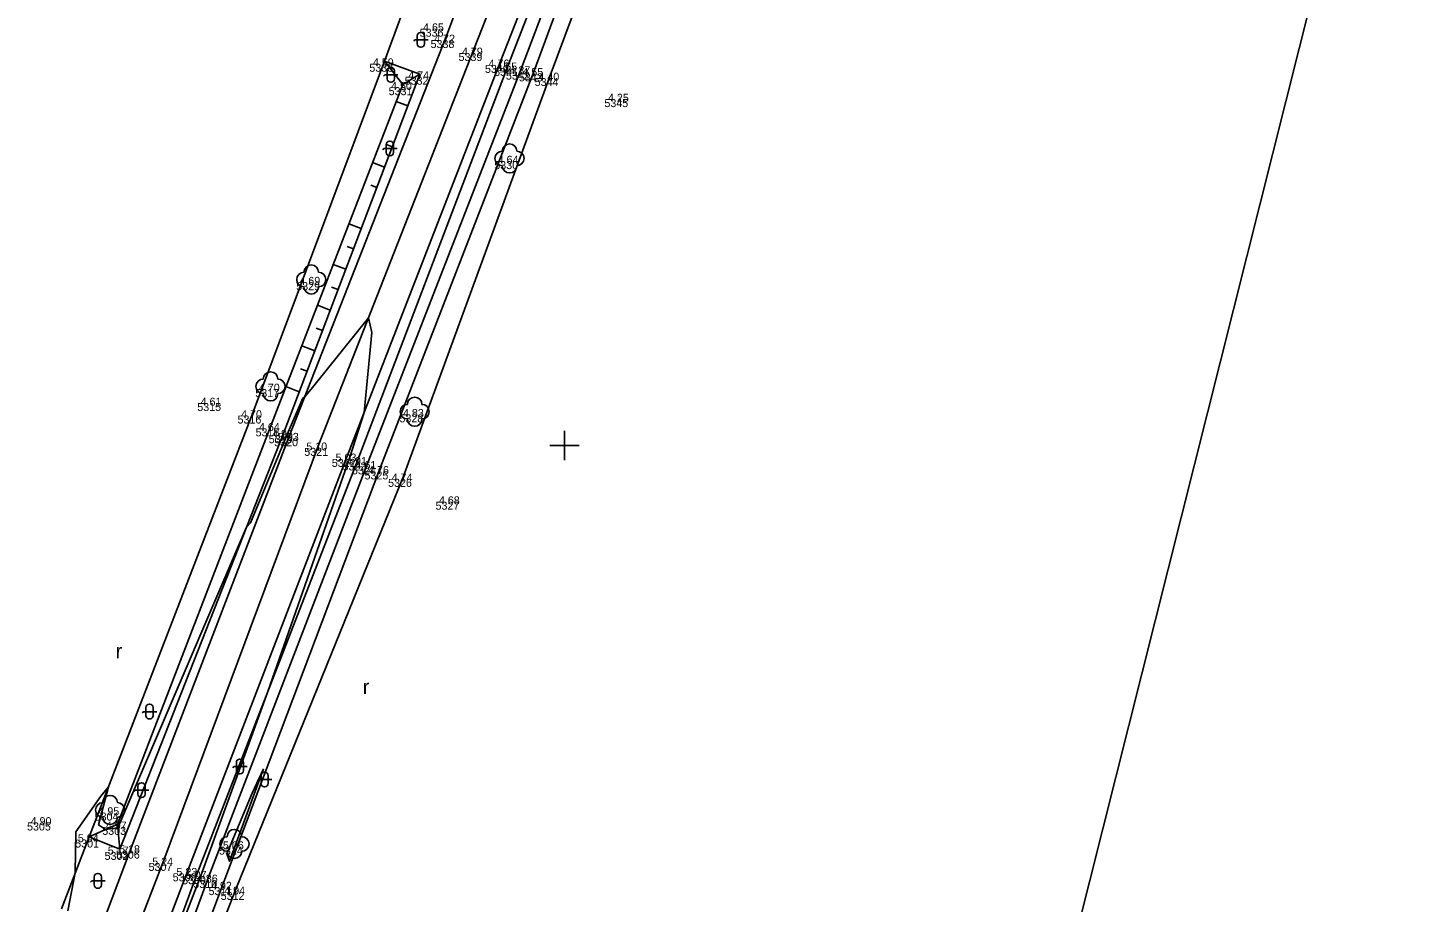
# Model space of a CAD drawing. Extents: x -740053 to -737517, y -1033516 to -1032488.
# Drawn here: x -739036.9 to -738942.4, y -1033331.4 to -1033271.3 of the extents above; entities that cross this region are included whole.
import ezdxf

# ---------------------------------------------------------------- set-up
doc = ezdxf.new("R2010")
doc.units = 0
for name, color, linetype in [('bod-cislo', 7, 'Continuous'), ('bod-oznac', 7, 'Continuous'), ('bod-vyska', 7, 'Continuous'), ('bod-vyska100', 7, 'Continuous'), ('Contours highlighted', 7, 'Continuous'), ('ctv-sit', 7, 'Continuous'), ('osa-komunikace', 7, 'Continuous'), ('Predmety bez rozlišeni', 7, 'Continuous'), ('rozhraní kultůr', 7, 'Continuous'), ('silnice', 7, 'Continuous'), ('Technické šrafy', 7, 'Continuous'), ('Terenni-hrana', 7, 'Continuous'), ('Znacky-kultury', 7, 'Continuous')]:
    doc.layers.add(name, color=color, linetype=linetype)

# ---------------------------------------------------------------- blocks, each defined once
blk = doc.blocks.new('POINT_DISPLAY')
blk.add_line((0, 0), (0, 0))
blk = doc.blocks.new('p_strom')
for centre, start, end in [((0, 1), 0, 180), ((-1, 0), 90, 270), ((1, 0), 270, 90), ((0, -1), 180, 0)]:
    blk.add_arc(centre, 1, start, end)
at = {"rotation": -180}
blk.add_blockref('POINT_DISPLAY', (0, 0), dxfattribs=at)
blk = doc.blocks.new('p_orna')
blk.add_text('r', height=2).set_placement((0, 0))
blk = doc.blocks.new('p_neplod')
for p, q in [((-0.82, 0), (-0.99, -0.18)), ((1, 0), (-0.82, 0)), ((-0.49, 0.56), (-0.49, -0.55)), ((0.05, 1.01), (-0.04, 1.01)), ((0.5, -0.55), (0.5, 0.56)), ((-0.04, -1), (0.05, -1))]:
    blk.add_line(p, q)
for centre, start, end in [((-0.04, 0.56), 90, 180), ((0.05, 0.56), 0, 90), ((-0.04, -0.55), 180, 270), ((0.05, -0.55), 270, 0)]:
    blk.add_arc(centre, 0.45, start, end)
blk = doc.blocks.new('ctvsit')
for p, q in [((0, -2), (0, 2)), ((2, 0), (-2, 0))]:
    blk.add_line(p, q)

msp = doc.modelspace()

# ---------------------------------------------------------------- linework, layer by layer
at = {"layer": 'Contours highlighted'}
for points in [[(-739026.523, -1033333.457), (-739024.99, -1033329.497), (-739020.42, -1033316.972), (-739014.765, -1033300.8), (-739013.78, -1033297.732), (-739013.244, -1033292.242), (-739013.478, -1033291.228), (-739017.328, -1033296.011), (-739017.87, -1033296.672), (-739017.982, -1033296.75), (-739019.056, -1033299.241), (-739021.58, -1033305.314), (-739021.861, -1033305.617), (-739030.706, -1033326.278), (-739031.561, -1033326.393), (-739032.034, -1033326.068), (-739031.348, -1033323.463), (-739031.882, -1033324.1), (-739033.593, -1033326.556), (-739033.63, -1033329.365), (-739034.156, -1033331.977)], [(-739020.692, -1033322.224), (-739021.471, -1033323.896), (-739023.224, -1033328.067), (-739023.037, -1033328.571), (-739020.692, -1033322.224)]]:
    msp.add_lwpolyline(points, dxfattribs=at)
at = {"layer": 'osa-komunikace'}
for p, q in [((-739006.25, -1033272.85), (-738996.046, -1033246.658)), ((-739016.92, -1033299.98), (-739006.25, -1033272.85)), ((-739027.55, -1033328.5), (-739016.92, -1033299.98)), ((-739033.19, -1033343.06), (-739027.55, -1033328.5))]:
    msp.add_line(p, q, dxfattribs=at)
at = {"layer": 'Predmety bez rozlišeni'}
msp.add_line((-738942.39, -1033244.461), (-738968.023, -1033346.284), dxfattribs=at)
at = {"layer": 'rozhraní kultůr'}
for p, q in [((-739000.99, -1033274.57), (-738991.17, -1033248.44)), ((-739011.08, -1033302.11), (-739000.99, -1033274.57)), ((-739022.59, -1033330.49), (-739011.08, -1033302.11)), ((-739028.19, -1033344.75), (-739022.59, -1033330.49))]:
    msp.add_line(p, q, dxfattribs=at)
at = {"layer": 'silnice'}
for p, q in [((-739008.16, -1033271.96), (-738991.07, -1033226.74)), ((-739004.42, -1033273.67), (-738994.08, -1033247.37)), ((-739018.91, -1033299.32), (-739008.16, -1033271.96)), ((-739014.95, -1033300.74), (-739004.42, -1033273.67)), ((-739029.79, -1033327.65), (-739018.91, -1033299.32)), ((-739025.89, -1033329.21), (-739014.95, -1033300.74)), ((-739035.4, -1033342.44), (-739029.79, -1033327.65)), ((-739031.46, -1033343.74), (-739025.89, -1033329.21))]:
    msp.add_line(p, q, dxfattribs=at)
at = {"layer": 'Technické šrafy'}
for p, q in [((-739010.774, -1033276.675), (-739011.573, -1033276.372)), ((-739011.84, -1033279.48), (-739012.248, -1033279.325)), ((-739012.373, -1033280.882), (-739013.197, -1033280.569)), ((-739012.906, -1033282.284), (-739013.322, -1033282.126)), ((-739013.971, -1033285.088), (-739014.821, -1033284.765)), ((-739014.504, -1033286.491), (-739014.933, -1033286.327)), ((-739015.037, -1033287.893), (-739015.904, -1033287.563)), ((-739015.57, -1033289.295), (-739016.008, -1033289.129)), ((-739016.103, -1033290.697), (-739016.987, -1033290.361)), ((-739016.636, -1033292.099), (-739017.082, -1033291.93)), ((-739017.169, -1033293.501), (-739018.069, -1033293.159)), ((-739017.701, -1033294.904), (-739018.156, -1033294.731)), ((-739018.234, -1033296.306), (-739019.152, -1033295.957))]:
    msp.add_line(p, q, dxfattribs=at)
at = {"layer": 'Terenni-hrana'}
for p, q in [((-739003.87, -1033273.88), (-738993.6, -1033247.56)), ((-739002.98, -1033274.13), (-738992.99, -1033247.82)), ((-739002.09, -1033274.25), (-738992.37, -1033248.04)), ((-739011.18, -1033270.36), (-739012.37, -1033273.59)), ((-739021.43, -1033297.76), (-739012.37, -1033273.59)), ((-739014.21, -1033300.98), (-739003.87, -1033273.88)), ((-739009.94, -1033274.48), (-739012.37, -1033273.59)), ((-739011.12, -1033275.2), (-739012.37, -1033273.59)), ((-739019.3, -1033299.11), (-739009.94, -1033274.48)), ((-739013.55, -1033301.25), (-739002.98, -1033274.13)), ((-739012.7, -1033301.6), (-739002.09, -1033274.25)), ((-739011.12, -1033275.2), (-739009.94, -1033274.48)), ((-739020.19, -1033298.64), (-739011.12, -1033275.2)), ((-739032.67, -1033326.89), (-739021.43, -1033297.76)), ((-739030.73, -1033326.02), (-739020.19, -1033298.64)), ((-739030.57, -1033327.74), (-739019.3, -1033299.11)), ((-739025.25, -1033329.41), (-739014.21, -1033300.98)), ((-739024.47, -1033329.67), (-739013.55, -1033301.25)), ((-739023.5, -1033330.16), (-739012.7, -1033301.6)), ((-739032.67, -1033326.89), (-739030.73, -1033326.02)), ((-739030.57, -1033327.74), (-739030.73, -1033326.02)), ((-739034.59, -1033331.84), (-739032.67, -1033326.89)), ((-739032.67, -1033326.89), (-739030.57, -1033327.74)), ((-739030.73, -1033344.15), (-739025.25, -1033329.41)), ((-739029.98, -1033344.44), (-739024.47, -1033329.67)), ((-739028.82, -1033344.48), (-739023.5, -1033330.16))]:
    msp.add_line(p, q, dxfattribs=at)

# ---------------------------------------------------------------- block references
at = {"layer": 'bod-oznac'}
for p in [(-739008.16, -1033271.96), (-739006.25, -1033272.85), (-739012.37, -1033273.59), (-739004.42, -1033273.67), (-739003.87, -1033273.88), (-739009.94, -1033274.48), (-739002.98, -1033274.13), (-739002.09, -1033274.25), (-739000.99, -1033274.57), (-739011.12, -1033275.2), (-738996.21, -1033276.02), (-739003.78, -1033280.28), (-739017.41, -1033288.6), (-739020.21, -1033295.94), (-739024.2, -1033296.9), (-739021.43, -1033297.76), (-739010.3, -1033297.68), (-739020.19, -1033298.64), (-739019.3, -1033299.11), (-739018.91, -1033299.32), (-739016.92, -1033299.98), (-739014.95, -1033300.74), (-739014.21, -1033300.98), (-739013.55, -1033301.25), (-739012.7, -1033301.6), (-739011.08, -1033302.11), (-739007.82, -1033303.68), (-739035.9, -1033325.72), (-739031.24, -1033325.04), (-739030.73, -1033326.02), (-739032.67, -1033326.89), (-739030.57, -1033327.74), (-739029.79, -1033327.65), (-739022.69, -1033327.38), (-739027.55, -1033328.5), (-739025.89, -1033329.21), (-739025.25, -1033329.41), (-739024.47, -1033329.67), (-739023.5, -1033330.16), (-739022.59, -1033330.49)]:
    msp.add_blockref('POINT_DISPLAY', p, dxfattribs=at)
at = {"layer": 'ctv-sit', "xscale": 0.5, "yscale": 0.5, "rotation": 180}
msp.add_blockref('ctvsit', (-739000, -1033300), dxfattribs=at)
at = {"layer": 'Znacky-kultury', "xscale": 0.5, "yscale": 0.5}
for name, p in [('p_neplod', (-739009.875, -1033272.127)), ('p_neplod', (-739011.949, -1033274.536)), ('p_neplod', (-739012.006, -1033279.599)), ('p_strom', (-739003.78, -1033280.28)), ('p_strom', (-739017.41, -1033288.6)), ('p_strom', (-739020.21, -1033295.94)), ('p_strom', (-739010.3, -1033297.68)), ('p_orna', (-739030.851, -1033314.621)), ('p_orna', (-739013.868, -1033317.08)), ('p_neplod', (-739028.531, -1033318.29)), ('p_neplod', (-739022.314, -1033322.067)), ('p_neplod', (-739020.619, -1033322.95)), ('p_neplod', (-739029.086, -1033323.684)), ('p_strom', (-739031.24, -1033325.04)), ('p_strom', (-739022.69, -1033327.38)), ('p_neplod', (-739032.087, -1033329.923))]:
    msp.add_blockref(name, p, dxfattribs=at)

# ---------------------------------------------------------------- texts
at = {"layer": 'bod-cislo'}
for s, p in [('5336', (-739009.958, -1033271.913)), ('5338', (-739009.208, -1033272.693)), ('5333', (-739013.418, -1033274.323)), ('5339', (-739007.285, -1033273.583)), ('5340', (-739005.468, -1033274.403)), ('5332', (-739010.988, -1033275.213)), ('5341', (-739004.839, -1033274.613)), ('5342', (-739004.028, -1033274.863)), ('5343', (-739003.138, -1033274.983)), ('5344', (-739002.051, -1033275.303)), ('5331', (-739012.089, -1033275.933)), ('5345', (-738997.258, -1033276.753)), ('5330', (-739004.828, -1033281.013)), ('5329', (-739018.445, -1033289.333)), ('5317', (-739021.258, -1033296.673)), ('5315', (-739025.248, -1033297.633)), ('5316', (-739022.478, -1033298.493)), ('5328', (-739011.348, -1033298.413)), ('5318', (-739021.238, -1033299.373)), ('5319', (-739020.335, -1033299.843)), ('5320', (-739019.958, -1033300.053)), ('5321', (-739017.889, -1033300.713)), ('5322', (-739015.998, -1033301.473)), ('5323', (-739015.258, -1033301.713)), ('5324', (-739014.611, -1033301.983)), ('5325', (-739013.748, -1033302.333)), ('5326', (-739012.128, -1033302.843)), ('5327', (-739008.868, -1033304.413)), ('5305', (-739036.948, -1033326.453)), ('5304', (-739032.301, -1033325.773)), ('5303', (-739031.778, -1033326.753)), ('5301', (-739033.639, -1033327.623)), ('5314', (-739023.751, -1033328.113)), ('5302', (-739031.618, -1033328.473)), ('5306', (-739030.838, -1033328.383)), ('5307', (-739028.598, -1033329.233)), ('5308', (-739026.938, -1033329.943)), ('5309', (-739026.285, -1033330.143)), ('5310', (-739025.518, -1033330.403)), ('5311', (-739024.469, -1033330.893)), ('5312', (-739023.638, -1033331.223))]:
    msp.add_text(s, height=0.55, dxfattribs=at).set_placement(p)
at = {"layer": 'bod-vyska'}
for s, p in [('4 65', (-739009.725, -1033271.547)), ('4 72', (-739008.962, -1033272.327)), ('4 79', (-739007.052, -1033273.217)), ('4 59', (-739013.172, -1033273.957)), ('4 76', (-739005.222, -1033274.037)), ('4 65', (-739004.685, -1033274.247)), ('4 74', (-739010.742, -1033274.847)), ('4 37', (-739003.782, -1033274.497)), ('4 55', (-739002.892, -1033274.617)), ('4 40', (-739001.792, -1033274.937)), ('4 50', (-739011.922, -1033275.567)), ('4 25', (-738997.012, -1033276.387)), ('4 64', (-739004.595, -1033280.647)), ('4 69', (-739018.225, -1033288.967)), ('4 70', (-739021.012, -1033296.307)), ('4 61', (-739025.015, -1033297.267)), ('4 83', (-739011.102, -1033298.047)), ('4 70', (-739022.232, -1033298.127)), ('4 64', (-739021.005, -1033299.007)), ('4 95', (-739020.102, -1033299.477)), ('5 03', (-739019.699, -1033299.687)), ('5 10', (-739017.748, -1033300.347)), ('5 03', (-739015.739, -1033301.107)), ('4 91', (-739015.012, -1033301.347)), ('4 61', (-739014.365, -1033301.617)), ('4 76', (-739013.502, -1033301.967)), ('4 74', (-739011.882, -1033302.477)), ('4 68', (-739008.635, -1033304.047)), ('4 95', (-739032.042, -1033325.407)), ('4 90', (-739036.702, -1033326.087)), ('4 97', (-739031.532, -1033326.387)), ('5 04', (-739033.459, -1033327.257)), ('5 17', (-739031.398, -1033328.107)), ('5 18', (-739030.618, -1033328.017)), ('5 06', (-739023.479, -1033327.747)), ('5 24', (-739028.339, -1033328.867)), ('5 23', (-739026.679, -1033329.577)), ('5 07', (-739026.039, -1033329.777)), ('4 86', (-739025.272, -1033330.037)), ('4 92', (-739024.302, -1033330.527)), ('4 94', (-739023.392, -1033330.857))]:
    msp.add_text(s, height=0.55, dxfattribs=at).set_placement(p)
at = {"layer": 'bod-vyska100'}
for s, p in [('304 72', (-739008.328, -1033271.993)), ('304 79', (-739006.418, -1033272.883)), ('304 59', (-739012.538, -1033273.623)), ('304 76', (-739004.588, -1033273.703)), ('304 65', (-739004.039, -1033273.913)), ('304 74', (-739010.108, -1033274.513)), ('304 37', (-739003.148, -1033274.163)), ('304 55', (-739002.258, -1033274.283)), ('304 40', (-739001.158, -1033274.603)), ('304 50', (-739011.288, -1033275.233)), ('304 25', (-738996.378, -1033276.053)), ('304 64', (-739003.949, -1033280.313)), ('304 69', (-739017.579, -1033288.633)), ('304 70', (-739020.378, -1033295.973)), ('304 61', (-739024.369, -1033296.933)), ('304 70', (-739021.598, -1033297.793)), ('304 83', (-739010.468, -1033297.713)), ('304 64', (-739020.359, -1033298.673)), ('304 95', (-739019.468, -1033299.143)), ('305 03', (-739019.077, -1033299.353)), ('305 10', (-739017.091, -1033300.013)), ('305 03', (-739015.117, -1033300.773)), ('304 91', (-739014.378, -1033301.013)), ('304 61', (-739013.719, -1033301.283)), ('304 76', (-739012.868, -1033301.633)), ('304 74', (-739011.248, -1033302.143)), ('304 68', (-739007.989, -1033303.713)), ('304 90', (-739036.068, -1033325.753)), ('304 95', (-739031.408, -1033325.073)), ('304 97', (-739030.898, -1033326.053)), ('305 04', (-739032.837, -1033326.923)), ('305 17', (-739030.741, -1033327.773)), ('305 18', (-739029.961, -1033327.683)), ('305 06', (-739022.857, -1033327.413)), ('305 24', (-739027.717, -1033328.533)), ('305 23', (-739026.057, -1033329.243)), ('305 07', (-739025.417, -1033329.443)), ('304 86', (-739024.638, -1033329.703)), ('304 92', (-739023.668, -1033330.193)), ('304 94', (-739022.758, -1033330.523))]:
    msp.add_text(s, height=0.05, dxfattribs=at).set_placement(p)

doc.saveas('drawing.dxf')
